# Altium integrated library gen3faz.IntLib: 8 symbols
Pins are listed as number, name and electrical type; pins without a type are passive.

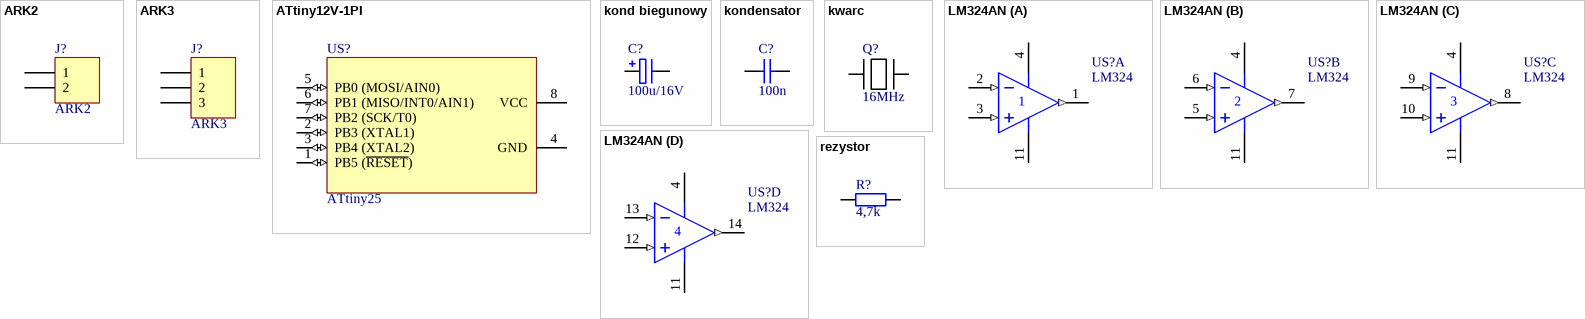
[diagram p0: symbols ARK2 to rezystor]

## ARK2
designator J?
footprint ARK2 3,5mm
footprint ARK2 5mm
footprint ARK2 7,5mm
pins: 1, 2

## ARK3
designator J?
footprint ARK3 3,5mm
footprint ARK3 5mm
footprint ARK3 7,5mm
pins: 1, 2, 3

## ATtiny12V-1PI
designator US?, comment ATtiny25
8-Bit AVR Microcontroller with 1K Byte of Flash Memory
footprint 8P3 (DIP; 8 Leads; Row Spacing 7.62 mm; Pitch 2.54 mm)
3D model 8P3 (DIP; 8 Leads; Row Spacing 7.62 mm; Pitch 2.54 mm)
pins: 1 PB5 (~{RESET}) (io), 2 PB3 (XTAL1) (io), 3 PB4 (XTAL2) (io), 4 GND (power), 5 PB0 (MOSI/AIN0) (io), 6 PB1 (MISO/INT0/AIN1) (io), 7 PB2 (SCK/T0) (io), 8 VCC (power)

## kond biegunowy
designator C?, comment 100u/16V
Polarized Capacitor
footprint Tantal B 3528-1411 (Capacitor, SM Tantalum; Body 3.5 x 2.8 mm (LxW typ))
footprint Tantal C 6032-2412 (Capacitor, SM Tantalum; Body 6.0 x 3.2 mm (LxW typ))
footprint Tantal D 7343-2917 (Capacitor, SM Tantalum; Body 7.3 x 4.3 mm (LxW typ))
footprint 2,5/5mm elektrolit
footprint 3,5/7mm elektrolit
footprint 5/10mm elektrolit
footprint 2,5/7mm elektrolit
footprint 7,5/16mm elektrolit
footprint 5/12,5mm elektrolit
footprint Tantal A 3216-1206 (Capacitor, SM Tantalum; Body 3.2 x 1.6 mm (LxW typ))
footprint A SMD elektrolit
footprint B SMD elektrolit
footprint C SMD elektrolit
footprint D SMD elektrolit
footprint E SMD elektrolit
footprint F SMD elektrolit
footprint 2,5/7mm le抗cy elektrolit
footprint 5/10mm le抗cy elektrolit
pins: 1, 2
1 alternate drawing of the same symbol

## kondensator
designator C?, comment 100n
footprint kond 2,5mm
footprint kond 7,5mm
footprint kond 10mm
footprint MELF-0805 (Metal Electrode Face (MELF) Resistor; Body 2 x 1.4 mm (LxDia))
footprint MELF-1206 (Metal Electrode Face (MELF) Resistor; Body 3.2 x 1.8 mm (LxDia))
footprint kond 15mm
footprint kond 5mm chudy
footprint kond 5mm gruby
footprint kond 5mm sredni
pins: 1, 2

## kwarc
designator Q?, comment 16MHz
footprint kwarc 5mm
footprint kwarc HC49
footprint kwarc 91SMX SMD
footprint kwarc 32768 le抗cy
footprint kwarc 32768 stojacy
pins: 1, 2

## LM324AN
designator US?, comment LM324
Quadruple Operational Amplifier
footprint N014 (DIP; 14 Leads; Row Spacing 7.62 mm; Pitch 2.54 mm)
3D model N014 (DIP; 14 Leads; Row Spacing 7.62 mm; Pitch 2.54 mm)
pins on every part: 4 V+ (power), 11 V- (power)
part A pins: 1 OUT (out), 2 IN- (in), 3 IN+ (in)
part B pins: 5 IN+ (in), 6 IN- (in), 7 OUT (out)
part C pins: 8 OUT (out), 9 IN- (in), 10 IN+ (in)
part D pins: 12 IN+ (in), 13 IN- (in), 14 OUT (out)

## rezystor
designator R?, comment 4,7k
footprint rez 7,5mm
footprint rez 10mm
footprint rez 12,5mm
footprint rez 15mm
footprint rez 17,5mm
footprint MELF-0805 (Metal Electrode Face (MELF) Resistor; Body 2 x 1.4 mm (LxDia))
footprint MELF-1206 (Metal Electrode Face (MELF) Resistor; Body 3.2 x 1.8 mm (LxDia))
footprint rez_bocznik 20mm
footprint rez_5W kostka
pins: 1, 2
